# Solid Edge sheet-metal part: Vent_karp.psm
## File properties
Author: Olev
Template: Normal.psm
Last saved by: Olev
Revision: 11
Application: Solid Edge
Accuracy: 0,990
Material Thickness: 0,30 mm
Bend Radius: 1,00 mm
Relief Width: 1,00 mm
Relief Length: 0,00 mm
Neutral Factor: 0,330
Minimum Arc Length: 0,10 mm
Deviational Tolerance: 0,10 mm
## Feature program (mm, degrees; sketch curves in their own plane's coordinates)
base tab "unnamed BaseTab 1"
flange "Flange_11"
flange "Flange_12"
flange "Flange_13"
flange "Flange_14"
flange "Flange_15"
flange "Flange_16"
flange "Flange_17"
flange "Flange_18"
louver "Louver_2"  LouverDepth = 1 mm; LouverHeight = 0.5 mm
pattern "unnamed Pattern 1" of "Louver_2"
louver "unnamed Louver 1"
louver "unnamed Louver 2"
louver "unnamed Louver 3"
louver "unnamed Louver 4"
louver "unnamed Louver 5"
louver "unnamed Louver 6"
louver "unnamed Louver 7"
louver "unnamed Louver 8"
louver "unnamed Louver 9"
louver "unnamed Louver 10"
pattern "unnamed Pattern 2" of "unnamed Louver 10"
louver "unnamed Louver 11"
louver "unnamed Louver 12"
louver "unnamed Louver 13"
louver "unnamed Louver 14"
louver "unnamed Louver 15"
louver "unnamed Louver 16"
louver "unnamed Louver 17"
louver "unnamed Louver 18"
louver "unnamed Louver 19"
bead "unnamed Bead 1"
bead "unnamed Bead 2"
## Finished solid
Body 1: solid body, 307 faces, 764 edges, 464 vertices.
  Faces by surface: plane 99, cylinder 80, sphere 80, cone 24, torus 24
  Edges by curve: circle 432, line 332
Bounding box of the edges (mm; curved faces can reach further): 35.350 x 22.300 x 12.300, from (-17.675, -0.5, -12) to (17.675, 21.8, 0.3).
Cylindrical faces by radius (mm): R0.3 x24, R0.95 x20, R1 x8, R1.25 x20, R1.3 x8
Conical faces (half-angle, radius in mm at the cone's reference point): 15 deg R0.0904 x6, 15 deg R0.1909 x6, 15 deg R0.3802 x6, 15 deg R0.4807 x6
Toroidal faces (ring radius, tube radius in mm): R0.15 r0.3 x12, R0.4807 r0.3 x12
Spherical faces by radius (mm): R0.95 x40, R1.25 x40
Planar faces by outward normal: +x 10, +y 4, +z 25, -x 10, -y 4, -z 22, oblique 24
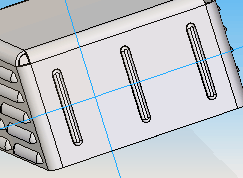
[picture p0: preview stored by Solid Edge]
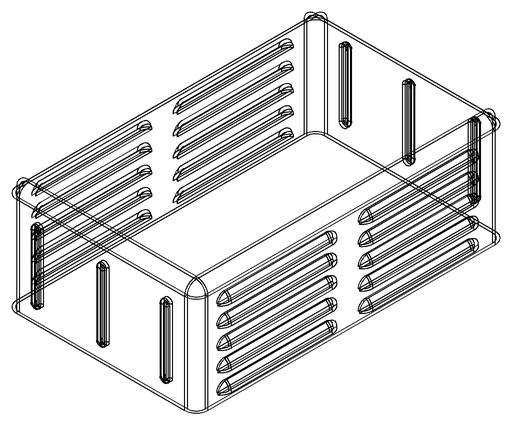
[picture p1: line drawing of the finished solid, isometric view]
